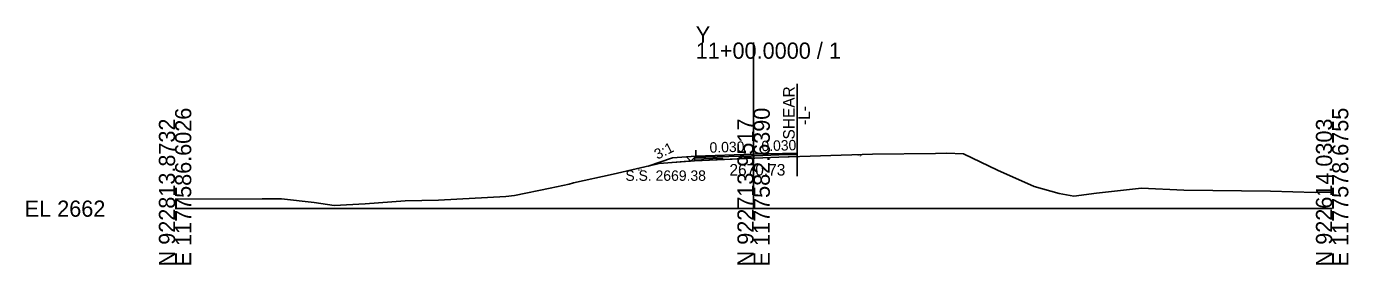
# Model space of a CAD drawing. Extents: x -26 to 203, y -10 to 2034.
# Drawn here: x -25.7 to 202.8, y 990.3 to 1031.6 of the extents above; entities that cross this region are included whole.
import ezdxf

# ---------------------------------------------------------------- set-up
doc = ezdxf.new("R2010")
doc.units = 0
for name, color, linetype in [('Exist Cross Section Cell', 7, 'Continuous'), ('Exist XS Center Line Elevation Label', 7, 'Continuous'), ('Exist XS Ground Line', 7, 'Continuous'), ('Prop XS Dump Level', 7, 'Continuous'), ('Prop XS Earthwork Shape', 7, 'Continuous'), ('Prop XS EOT Tick Mark', 7, 'Continuous'), ('Prop XS Finish Grade', 7, 'Continuous'), ('Prop XS Finish Grade Earthwork', 7, 'Continuous'), ('Prop XS Finish Grade Pavement', 7, 'Continuous'), ('Prop XS Pvmt Edge Slope', 7, 'Continuous'), ('Prop XS SE Text', 7, 'Continuous'), ('Prop XS Side Slope Text', 7, 'Continuous'), ('Prop XS SS Elevation Text', 7, 'Continuous'), ('Prop XS Subgrade Earthwork', 7, 'Continuous'), ('Prop XS Vertical Lines', 7, 'Continuous'), ('Prop XS Vertical Lines Alignments', 7, 'Continuous'), ('Prop XS Wedging', 7, 'Continuous')]:
    doc.layers.add(name, color=color, linetype=linetype)

msp = doc.modelspace()

# ---------------------------------------------------------------- linework, layer by layer
at = {"layer": 'Exist Cross Section Cell'}
for p, q in [((100, 1000), (100, 1028.77)), ((0, 1000), (100, 1000)), ((100, 1000), (200, 1000))]:
    msp.add_line(p, q, dxfattribs=at)
at = {"layer": 'Exist XS Ground Line'}
for p, q in [((83.69, 1007.82), (85.2, 1007.92)), ((85.2, 1007.92), (89.81, 1008.29)), ((89.81, 1008.29), (100.19, 1008.74)), ((100.19, 1008.74), (104.34, 1008.92)), ((104.34, 1008.92), (111.58, 1009.14)), ((111.58, 1009.14), (120.58, 1009.46)), ((120.58, 1009.46), (131.46, 1009.57)), ((131.46, 1009.57), (133.36, 1009.59)), ((133.36, 1009.59), (136.3, 1009.47)), ((136.3, 1009.47), (142.16, 1006.69)), ((68.85, 1004.48), (75.72, 1005.98)), ((75.72, 1005.98), (83.69, 1007.82)), ((142.16, 1006.69), (148.49, 1003.84)), ((58.65, 1002.29), (64.86, 1003.54)), ((64.86, 1003.54), (68.13, 1004.24)), ((68.13, 1004.24), (68.85, 1004.48)), ((148.49, 1003.84), (152.81, 1002.65)), ((159.25, 1002.68), (167.07, 1003.55)), ((167.07, 1003.55), (174.39, 1003.22)), ((0, 1001.66), (15.06, 1001.71)), ((15.06, 1001.71), (18.39, 1001.73)), ((18.39, 1001.73), (24.07, 1001.09)), ((24.07, 1001.09), (27.51, 1000.53)), ((32.88, 1000.86), (39.75, 1001.33)), ((39.75, 1001.33), (45.55, 1001.49)), ((45.55, 1001.49), (57.17, 1002.08)), ((57.17, 1002.08), (58.65, 1002.29)), ((152.81, 1002.65), (154.1, 1002.39)), ((154.1, 1002.39), (155.33, 1002.18)), ((155.33, 1002.18), (159.25, 1002.68)), ((174.39, 1003.22), (189.36, 1003.03)), ((189.36, 1003.03), (197.06, 1002.82)), ((197.06, 1002.82), (200, 1002.83)), ((27.51, 1000.53), (32.88, 1000.86))]:
    msp.add_line(p, q, dxfattribs=at)
at = {"layer": 'Prop XS Dump Level'}
for p, q in [((100, 1009.41), (90, 1009.11)), ((107.52, 1009.63), (100, 1009.41))]:
    msp.add_line(p, q, dxfattribs=at)
at = {"layer": 'Prop XS Earthwork Shape'}
for p, q in [((86, 1008.79), (81.78, 1007.38)), ((83.69, 1007.82), (85.2, 1007.92)), ((85.2, 1007.92), (89.44, 1008.26)), ((88.41, 1008.98), (86, 1008.79)), ((89.14, 1008.25), (88.41, 1008.98)), ((89.44, 1008.26), (89.14, 1008.25)), ((81.78, 1007.38), (83.69, 1007.82))]:
    msp.add_line(p, q, dxfattribs=at)
at = {"layer": 'Prop XS EOT Tick Mark'}
for p, q in [((107.52, 1009.63), (107.52, 1010.63)), ((90, 1009.11), (90, 1010.11))]:
    msp.add_line(p, q, dxfattribs=at)
at = {"layer": 'Prop XS Finish Grade'}
msp.add_line((90, 1009.11), (88.41, 1008.98), dxfattribs=at)
at = {"layer": 'Prop XS Finish Grade Earthwork'}
for p, q in [((86, 1008.79), (81.78, 1007.38)), ((88.41, 1008.98), (86, 1008.79))]:
    msp.add_line(p, q, dxfattribs=at)
at = {"layer": 'Prop XS Finish Grade Pavement'}
for p, q in [((90, 1009.11), (100, 1009.41)), ((100, 1009.41), (107.52, 1009.63))]:
    msp.add_line(p, q, dxfattribs=at)
at = {"layer": 'Prop XS Pvmt Edge Slope'}
for p, q in [((90, 1009.11), (89.14, 1008.25)), ((107.52, 1009.63), (107.52, 1009))]:
    msp.add_line(p, q, dxfattribs=at)
at = {"layer": 'Prop XS Subgrade Earthwork'}
for p, q in [((89.14, 1008.25), (88.41, 1008.98)), ((89.44, 1008.26), (89.14, 1008.25)), ((107.52, 1008.8), (107.52, 1009))]:
    msp.add_line(p, q, dxfattribs=at)
at = {"layer": 'Prop XS Vertical Lines'}
msp.add_line((107.52, 1021.65), (107.52, 1005.65), dxfattribs=at)
at = {"layer": 'Prop XS Wedging'}
for points in [[(89.81, 1008.29), (89.81, 1008.85), (99.63, 1009.15), (100.19, 1009.16), (104.34, 1009.3), (107.52, 1009.4), (107.52, 1009.02), (104.34, 1008.92), (100.19, 1008.74), (99.63, 1008.72)], [(89.81, 1008.29), (89.81, 1008.85), (99.63, 1009.15), (100.19, 1009.16), (104.34, 1009.3), (107.52, 1009.4), (107.52, 1009.02), (104.34, 1008.92), (100.19, 1008.74), (99.63, 1008.72)], [(89.81, 1008.29), (89.81, 1008.6), (94.55, 1008.74), (94.79, 1008.5)]]:
    msp.add_lwpolyline(points, close=True, dxfattribs=at)

# ---------------------------------------------------------------- texts
at = {"layer": 'Exist Cross Section Cell'}
for s, p in [('Y', (90, 1028.77)), ('11+00.0000 / 1', (90, 1025.97)), ('EL 2662', (-26, 998.6))]:
    msp.add_text(s, height=2.8, dxfattribs=at).set_placement(p)
for s, p in [('E 1177586.6026', (2.8, 990)), ('E 1177582.6390', (102.8, 990)), ('E 1177578.6755', (202.8, 990)), ('N 922813.8732', (0, 990)), ('N 922713.9517', (100, 990)), ('N 922614.0303', (200, 990))]:
    msp.add_text(s, height=2.8, rotation=90, dxfattribs=at).set_placement(p)
at = {"layer": 'Exist XS Center Line Elevation Label'}
msp.add_text('2670.73', height=2, dxfattribs=at).set_placement((95.82, 1005.73))
at = {"layer": 'Prop XS Dump Level'}
for s, height, p in [('Case1', 0.04, (86, 1008.75)), ('Case1', 0.04, (111.94, 1009.49)), ('Eop', 0.3, (117.94, 1009.04)), ('Eop', 0.3, (80, 1006.58))]:
    msp.add_text(s, height=height, dxfattribs=at).set_placement(p)
at = {"layer": 'Prop XS SE Text'}
for p in [(92.41, 1009.68), (101.38, 1009.95)]:
    msp.add_text('0.030', height=1.8, rotation=1.7184, dxfattribs=at).set_placement(p)
at = {"layer": 'Prop XS Side Slope Text'}
msp.add_text('3:1', height=1.8, rotation=26.5651, dxfattribs=at).set_placement((83.38, 1008.47))
at = {"layer": 'Prop XS SS Elevation Text'}
msp.add_text('S.S. 2669.38', height=1.8, dxfattribs=at).set_placement((77.84, 1004.82))
at = {"layer": 'Prop XS Vertical Lines Alignments'}
for s, p in [('SHEAR', (107.1, 1011.98)), ('-L-', (109.72, 1014.5))]:
    msp.add_text(s, height=2, rotation=90, dxfattribs=at).set_placement(p)

doc.saveas('drawing.dxf')
